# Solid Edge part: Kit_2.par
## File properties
Author: ahadarics
Last saved by: ahadarics
Revision: 76
Sűrűség: 0,000 kg/m^3
Pontosság: 0,990
Username: ahadarics
Dokumentum tartalom típus: 0
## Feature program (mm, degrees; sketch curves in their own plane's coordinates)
base feature "unnamed BaseFeature 1"
sketch for "Furat_1" plane through (0, 3.75, 13.5) normal (0, 0, 1) x-axis (0, 1, 0)
  hole centre (-0.25, 0) bore radius 4.283
hole "Furat_1" nominal diameter 9.728 finite  ThreadDepth = 7.5 mm
chamfer "Letörés_1" setback 0.7
sketch for "unnamed Protrusion 1" #1 plane through (0, 33.5, 0) normal (0, 1, 0) x-axis (0, 0, -1)
  line (-7.5498, -8) -> (7.5498, -8)
  arc centre (0, 0) radius 11 from (7.5498, -8) to (-7.5498, -8) cw
sketch for "unnamed Protrusion 1" #2 plane through (0, 33.5, 0) normal (0, 1, 0) x-axis (0, 0, -1)
  line (-7.5498, 8) -> (7.5498, 8)
extrude "unnamed Protrusion 1" add to key point along -normal
thread "unnamed Thread 1"
chamfer "Letörés_2" setback 1.5
sketch for "Kivágás_1" #1 plane through (0, 33.5, 0) normal (0, 1, 0) x-axis (0, 0, -1)
  line (-7.5498, -8) -> (7.5498, -8)
  arc centre (0, 0) radius 11 from (7.5498, -8) to (-7.5498, -8) cw
sketch for "Kivágás_1" #2 plane through (0, 33.5, 0) normal (0, 1, 0) x-axis (0, 0, -1)
  line (-7.5498, 8) -> (7.5498, 8)
extrude "Kivágás_1" cut finite 20 along -normal
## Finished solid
Body 1: solid body, 32 faces, 72 edges, 41 vertices.
  Faces by surface: plane 13, cylinder 11, cone 8
  Edges by curve: line 33, circle 31, intersection 4, spline 4
Bounding box of the edges (mm): 30.000 x 39.500 x 28.500, from (-15, -6, -15) to (15, 33.5, 13.5).
Cylindrical faces by radius (mm): R4 x1, R4.28 x1, R4.283 x1, R9.85 x2, R11 x4, R13.5 x1, R15 x1
Conical faces (half-angle, radius in mm at the cone's reference point): 45 deg R4.1 x2, 45 deg R4.983 x1, 45 deg R11 x2, 59 deg R2.1415 x1, 60 deg R10.425 x2
Planar faces by outward normal: +x 1, +y 7, +z 2, -x 1, -y 2
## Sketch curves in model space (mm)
arc centre (0, 33.5, 0) radius 11 from (8, 33.5, -7.5498) through (11, 33.5, 0) to (8, 33.5, 7.5498)
line (8, 33.5, 7.5498) -> (8, 33.5, -7.5498)
arc centre (0, 33.5, 0) radius 11 from (-8, 33.5, 7.5498) through (-11, 33.5, 0) to (-8, 33.5, -7.5498)
line (-8, 33.5, 7.5498) -> (-8, 33.5, -7.5498)
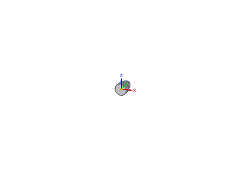
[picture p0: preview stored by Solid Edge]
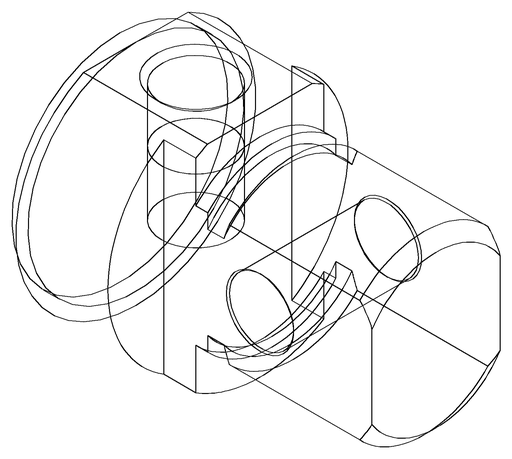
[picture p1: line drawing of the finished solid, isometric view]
